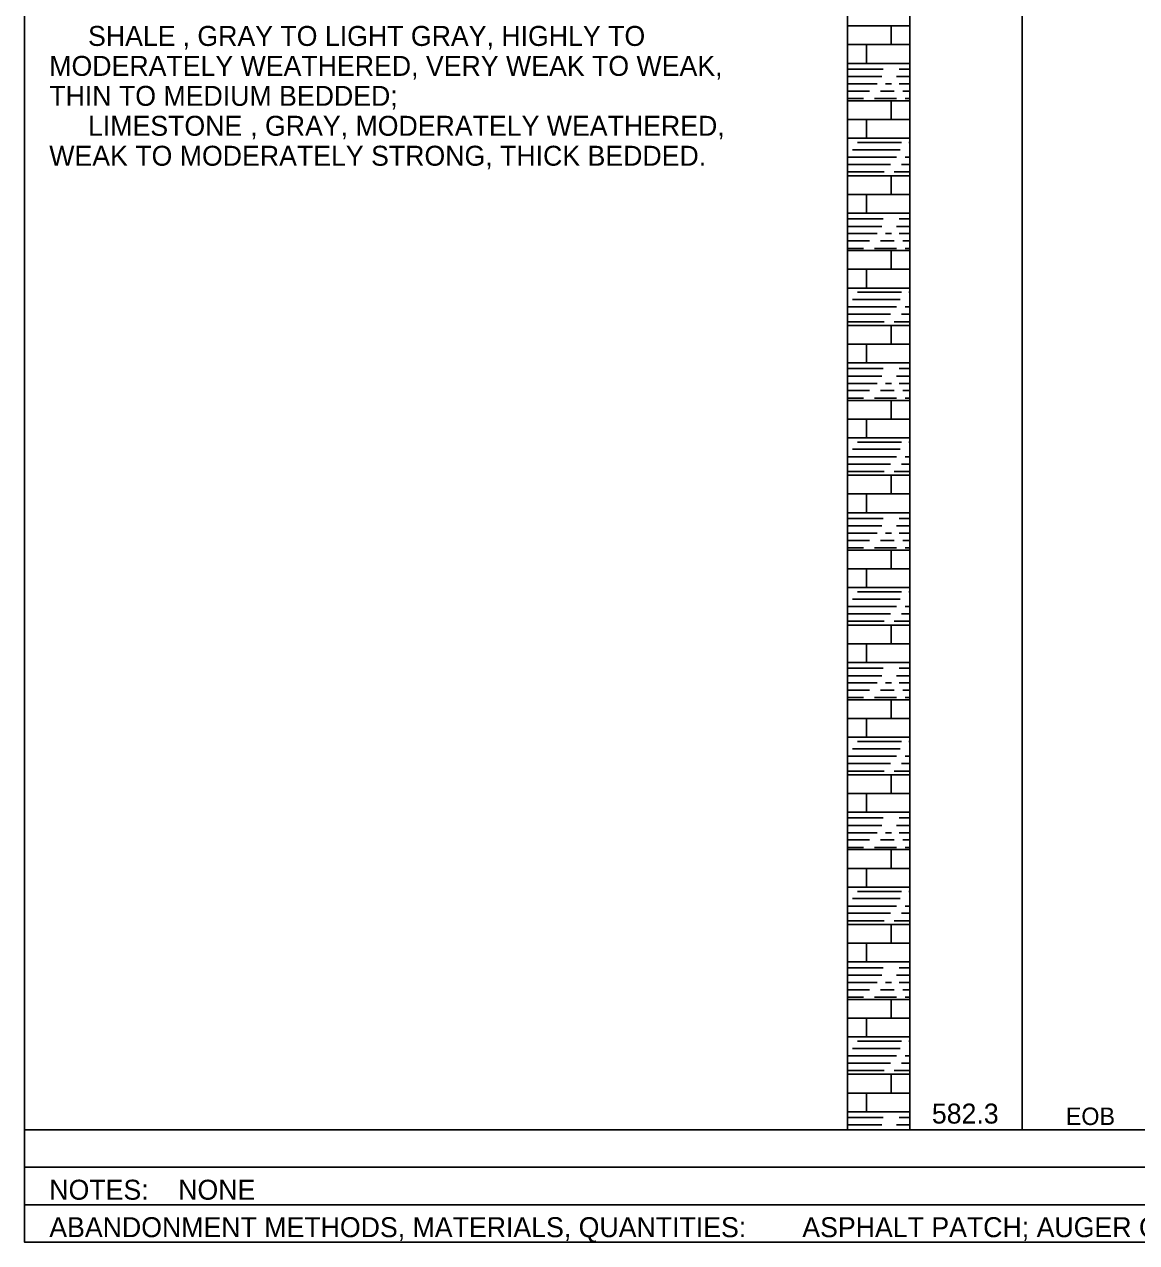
# Model space of a CAD drawing. Extents: x 0 to 0.833, y -0.323 to 0.608.
# Drawn here: x 0 to 0.3715, y -0.3234 to 0.0833 of the extents above; entities that cross this region are included whole.
import ezdxf

# ---------------------------------------------------------------- set-up
doc = ezdxf.new("R2010")
doc.units = 0

msp = doc.modelspace()

# ---------------------------------------------------------------- linework, layer by layer
msp.add_lwpolyline([(0, -0.32328), (0.83333, -0.32328), (0.83333, 0.60833), (0, 0.60833)], close=True)
for points in [[(0.29583, 0.55417), (0.29583, -0.28575)], [(0.29583, 0.55417), (0.29583, -0.28575)], [(0.33333, 0.55417), (0.33333, -0.28575)], [(0.33333, 0.55417), (0.33333, -0.28575)], [(0.275, 0.52917), (0.275, -0.28575)], [(0.275, 0.09525), (0.275, -0.28575)], [(0.275, 0.08275), (0.29583, 0.08275)], [(0.28958, 0.0765), (0.28958, 0.08275)], [(0.275, 0.0765), (0.29583, 0.0765)], [(0.28125, 0.07025), (0.28125, 0.0765)], [(0.275, 0.07025), (0.29583, 0.07025)], [(0.275, 0.06833), (0.28683, 0.06833)], [(0.275, 0.06583), (0.28642, 0.06583)], [(0.29133, 0.06583), (0.29583, 0.06583)], [(0.29217, 0.06833), (0.29583, 0.06833)], [(0.275, 0.06342), (0.28483, 0.06342)], [(0.28767, 0.06342), (0.28967, 0.06342)], [(0.29217, 0.06342), (0.29583, 0.06342)], [(0.275, 0.061), (0.28233, 0.061)], [(0.275, 0.0585), (0.28033, 0.0585)], [(0.275, 0.05775), (0.29583, 0.05775)], [(0.284, 0.0585), (0.29133, 0.0585)], [(0.286, 0.061), (0.2905, 0.061)], [(0.28958, 0.0515), (0.28958, 0.05775)], [(0.29342, 0.061), (0.29583, 0.061)], [(0.29417, 0.0585), (0.29583, 0.0585)], [(0.275, 0.0515), (0.29583, 0.0515)], [(0.28125, 0.04525), (0.28125, 0.0515)], [(0.275, 0.04525), (0.29583, 0.04525)], [(0.27667, 0.04142), (0.29258, 0.04142)], [(0.27825, 0.04383), (0.293, 0.04383)], [(0.29542, 0.04383), (0.29583, 0.04383)], [(0.275, 0.03892), (0.29133, 0.03892)], [(0.29417, 0.03892), (0.29583, 0.03892)], [(0.275, 0.0365), (0.28933, 0.0365)], [(0.275, 0.034), (0.28725, 0.034)], [(0.275, 0.03275), (0.29583, 0.03275)], [(0.28958, 0.0265), (0.28958, 0.03275)], [(0.2905, 0.034), (0.29583, 0.034)], [(0.293, 0.0365), (0.29583, 0.0365)], [(0.275, 0.0265), (0.29583, 0.0265)], [(0.28125, 0.02025), (0.28125, 0.0265)], [(0.275, 0.02025), (0.29583, 0.02025)], [(0.275, 0.01833), (0.28683, 0.01833)], [(0.29217, 0.01833), (0.29583, 0.01833)], [(0.275, 0.01583), (0.28642, 0.01583)], [(0.275, 0.01342), (0.28483, 0.01342)], [(0.28767, 0.01342), (0.28967, 0.01342)], [(0.29133, 0.01583), (0.29583, 0.01583)], [(0.29217, 0.01342), (0.29583, 0.01342)], [(0.275, 0.011), (0.28233, 0.011)], [(0.275, 0.0085), (0.28033, 0.0085)], [(0.284, 0.0085), (0.29133, 0.0085)], [(0.286, 0.011), (0.2905, 0.011)], [(0.29342, 0.011), (0.29583, 0.011)], [(0.29417, 0.0085), (0.29583, 0.0085)], [(0.275, 0.00775), (0.29583, 0.00775)], [(0.28958, 0.0015), (0.28958, 0.00775)], [(0.275, 0.0015), (0.29583, 0.0015)], [(0.28125, -0.00475), (0.28125, 0.0015)], [(0.275, -0.00475), (0.29583, -0.00475)], [(0.27825, -0.00617), (0.293, -0.00617)], [(0.29542, -0.00617), (0.29583, -0.00617)], [(0.275, -0.01108), (0.29133, -0.01108)], [(0.27667, -0.00858), (0.29258, -0.00858)], [(0.29417, -0.01108), (0.29583, -0.01108)], [(0.275, -0.0135), (0.28933, -0.0135)], [(0.275, -0.016), (0.28725, -0.016)], [(0.2905, -0.016), (0.29583, -0.016)], [(0.293, -0.0135), (0.29583, -0.0135)], [(0.275, -0.01725), (0.29583, -0.01725)], [(0.28958, -0.0235), (0.28958, -0.01725)], [(0.275, -0.0235), (0.29583, -0.0235)], [(0.28125, -0.02975), (0.28125, -0.0235)], [(0.275, -0.02975), (0.29583, -0.02975)], [(0.275, -0.03167), (0.28683, -0.03167)], [(0.29217, -0.03167), (0.29583, -0.03167)], [(0.275, -0.03417), (0.28642, -0.03417)], [(0.275, -0.03658), (0.28483, -0.03658)], [(0.28767, -0.03658), (0.28967, -0.03658)], [(0.29133, -0.03417), (0.29583, -0.03417)], [(0.29217, -0.03658), (0.29583, -0.03658)], [(0.275, -0.039), (0.28233, -0.039)], [(0.286, -0.039), (0.2905, -0.039)], [(0.29342, -0.039), (0.29583, -0.039)], [(0.275, -0.0415), (0.28033, -0.0415)], [(0.275, -0.04225), (0.29583, -0.04225)], [(0.284, -0.0415), (0.29133, -0.0415)], [(0.28958, -0.0485), (0.28958, -0.04225)], [(0.29417, -0.0415), (0.29583, -0.0415)], [(0.275, -0.0485), (0.29583, -0.0485)], [(0.28125, -0.05475), (0.28125, -0.0485)], [(0.275, -0.05475), (0.29583, -0.05475)], [(0.27825, -0.05617), (0.293, -0.05617)], [(0.29542, -0.05617), (0.29583, -0.05617)], [(0.27667, -0.05858), (0.29258, -0.05858)], [(0.275, -0.06108), (0.29133, -0.06108)], [(0.275, -0.0635), (0.28933, -0.0635)], [(0.293, -0.0635), (0.29583, -0.0635)], [(0.29417, -0.06108), (0.29583, -0.06108)], [(0.275, -0.066), (0.28725, -0.066)], [(0.275, -0.06725), (0.29583, -0.06725)], [(0.28958, -0.0735), (0.28958, -0.06725)], [(0.2905, -0.066), (0.29583, -0.066)], [(0.275, -0.0735), (0.29583, -0.0735)], [(0.28125, -0.07975), (0.28125, -0.0735)], [(0.275, -0.07975), (0.29583, -0.07975)], [(0.275, -0.08167), (0.28683, -0.08167)], [(0.275, -0.08417), (0.28642, -0.08417)], [(0.29133, -0.08417), (0.29583, -0.08417)], [(0.29217, -0.08167), (0.29583, -0.08167)], [(0.275, -0.08658), (0.28483, -0.08658)], [(0.275, -0.089), (0.28233, -0.089)], [(0.286, -0.089), (0.2905, -0.089)], [(0.28767, -0.08658), (0.28967, -0.08658)], [(0.29217, -0.08658), (0.29583, -0.08658)], [(0.29342, -0.089), (0.29583, -0.089)], [(0.275, -0.0915), (0.28033, -0.0915)], [(0.275, -0.09225), (0.29583, -0.09225)], [(0.284, -0.0915), (0.29133, -0.0915)], [(0.28958, -0.0985), (0.28958, -0.09225)], [(0.29417, -0.0915), (0.29583, -0.0915)], [(0.275, -0.0985), (0.29583, -0.0985)], [(0.28125, -0.10475), (0.28125, -0.0985)], [(0.275, -0.10475), (0.29583, -0.10475)], [(0.27667, -0.10858), (0.29258, -0.10858)], [(0.27825, -0.10617), (0.293, -0.10617)], [(0.29542, -0.10617), (0.29583, -0.10617)], [(0.275, -0.11108), (0.29133, -0.11108)], [(0.275, -0.1135), (0.28933, -0.1135)], [(0.293, -0.1135), (0.29583, -0.1135)], [(0.29417, -0.11108), (0.29583, -0.11108)], [(0.275, -0.116), (0.28725, -0.116)], [(0.275, -0.11725), (0.29583, -0.11725)], [(0.28958, -0.1235), (0.28958, -0.11725)], [(0.2905, -0.116), (0.29583, -0.116)], [(0.275, -0.1235), (0.29583, -0.1235)], [(0.28125, -0.12975), (0.28125, -0.1235)], [(0.275, -0.12975), (0.29583, -0.12975)], [(0.275, -0.13167), (0.28683, -0.13167)], [(0.275, -0.13417), (0.28642, -0.13417)], [(0.29133, -0.13417), (0.29583, -0.13417)], [(0.29217, -0.13167), (0.29583, -0.13167)], [(0.275, -0.13658), (0.28483, -0.13658)], [(0.28767, -0.13658), (0.28967, -0.13658)], [(0.29217, -0.13658), (0.29583, -0.13658)], [(0.275, -0.139), (0.28233, -0.139)], [(0.275, -0.1415), (0.28033, -0.1415)], [(0.275, -0.14225), (0.29583, -0.14225)], [(0.284, -0.1415), (0.29133, -0.1415)], [(0.286, -0.139), (0.2905, -0.139)], [(0.28958, -0.1485), (0.28958, -0.14225)], [(0.29342, -0.139), (0.29583, -0.139)], [(0.29417, -0.1415), (0.29583, -0.1415)], [(0.275, -0.1485), (0.29583, -0.1485)], [(0.28125, -0.15475), (0.28125, -0.1485)], [(0.275, -0.15475), (0.29583, -0.15475)], [(0.27667, -0.15858), (0.29258, -0.15858)], [(0.27825, -0.15617), (0.293, -0.15617)], [(0.29542, -0.15617), (0.29583, -0.15617)], [(0.275, -0.16108), (0.29133, -0.16108)], [(0.29417, -0.16108), (0.29583, -0.16108)], [(0.275, -0.1635), (0.28933, -0.1635)], [(0.275, -0.166), (0.28725, -0.166)], [(0.2905, -0.166), (0.29583, -0.166)], [(0.293, -0.1635), (0.29583, -0.1635)], [(0.275, -0.16725), (0.29583, -0.16725)], [(0.28958, -0.1735), (0.28958, -0.16725)], [(0.275, -0.1735), (0.29583, -0.1735)], [(0.28125, -0.17975), (0.28125, -0.1735)], [(0.275, -0.17975), (0.29583, -0.17975)], [(0.275, -0.18167), (0.28683, -0.18167)], [(0.29217, -0.18167), (0.29583, -0.18167)], [(0.275, -0.18417), (0.28642, -0.18417)], [(0.275, -0.18658), (0.28483, -0.18658)], [(0.28767, -0.18658), (0.28967, -0.18658)], [(0.29133, -0.18417), (0.29583, -0.18417)], [(0.29217, -0.18658), (0.29583, -0.18658)], [(0.275, -0.189), (0.28233, -0.189)], [(0.286, -0.189), (0.2905, -0.189)], [(0.29342, -0.189), (0.29583, -0.189)], [(0.275, -0.1915), (0.28033, -0.1915)], [(0.275, -0.19225), (0.29583, -0.19225)], [(0.284, -0.1915), (0.29133, -0.1915)], [(0.28958, -0.1985), (0.28958, -0.19225)], [(0.29417, -0.1915), (0.29583, -0.1915)], [(0.275, -0.1985), (0.29583, -0.1985)], [(0.28125, -0.20475), (0.28125, -0.1985)], [(0.275, -0.20475), (0.29583, -0.20475)], [(0.27825, -0.20617), (0.293, -0.20617)], [(0.29542, -0.20617), (0.29583, -0.20617)], [(0, -0.21078), (0, -0.32328), (0.83333, -0.32328), (0.83333, -0.21078)], [(0.275, -0.21108), (0.29133, -0.21108)], [(0.27667, -0.20858), (0.29258, -0.20858)], [(0.29417, -0.21108), (0.29583, -0.21108)], [(0.275, -0.2135), (0.28933, -0.2135)], [(0.293, -0.2135), (0.29583, -0.2135)], [(0.275, -0.216), (0.28725, -0.216)], [(0.275, -0.21725), (0.29583, -0.21725)], [(0.28958, -0.2235), (0.28958, -0.21725)], [(0.2905, -0.216), (0.29583, -0.216)], [(0.275, -0.2235), (0.29583, -0.2235)], [(0.28125, -0.22975), (0.28125, -0.2235)], [(0.275, -0.22975), (0.29583, -0.22975)], [(0.275, -0.23167), (0.28683, -0.23167)], [(0.29217, -0.23167), (0.29583, -0.23167)], [(0.275, -0.23417), (0.28642, -0.23417)], [(0.29133, -0.23417), (0.29583, -0.23417)], [(0.275, -0.23658), (0.28483, -0.23658)], [(0.275, -0.239), (0.28233, -0.239)], [(0.286, -0.239), (0.2905, -0.239)], [(0.28767, -0.23658), (0.28967, -0.23658)], [(0.29217, -0.23658), (0.29583, -0.23658)], [(0.29342, -0.239), (0.29583, -0.239)], [(0.275, -0.2415), (0.28033, -0.2415)], [(0.275, -0.24225), (0.29583, -0.24225)], [(0.284, -0.2415), (0.29133, -0.2415)], [(0.28958, -0.2485), (0.28958, -0.24225)], [(0.29417, -0.2415), (0.29583, -0.2415)], [(0.275, -0.2485), (0.29583, -0.2485)], [(0.28125, -0.25475), (0.28125, -0.2485)], [(0.275, -0.25475), (0.29583, -0.25475)], [(0.27825, -0.25617), (0.293, -0.25617)], [(0.29542, -0.25617), (0.29583, -0.25617)], [(0.27667, -0.25858), (0.29258, -0.25858)], [(0.275, -0.26108), (0.29133, -0.26108)], [(0.275, -0.2635), (0.28933, -0.2635)], [(0.293, -0.2635), (0.29583, -0.2635)], [(0.29417, -0.26108), (0.29583, -0.26108)], [(0.275, -0.266), (0.28725, -0.266)], [(0.275, -0.26725), (0.29583, -0.26725)], [(0.28958, -0.2735), (0.28958, -0.26725)], [(0.2905, -0.266), (0.29583, -0.266)], [(0.275, -0.2735), (0.29583, -0.2735)], [(0.28125, -0.27975), (0.28125, -0.2735)], [(0.275, -0.27975), (0.29583, -0.27975)], [(0.275, -0.28167), (0.28683, -0.28167)], [(0.275, -0.28417), (0.28642, -0.28417)], [(0.29133, -0.28417), (0.29583, -0.28417)], [(0.29217, -0.28167), (0.29583, -0.28167)], [(0, -0.28575), (0.275, -0.28575)], [(0.275, -0.28575), (0.29583, -0.28575)], [(0.275, -0.28575), (0.29583, -0.28575)], [(0.29583, -0.28575), (0.33333, -0.28575)], [(0.33333, -0.28575), (0.37917, -0.28575)], [(0, -0.29828), (0.83333, -0.29828)], [(0, -0.31078), (0.83333, -0.31078)]]:
    msp.add_lwpolyline(points)

# ---------------------------------------------------------------- texts
for s, height, p in [('SHALE', 0.006667, (0.02127, 0.07608)), (', GRAY TO LIGHT GRAY, HIGHLY TO', 0.0066667, (0.05284, 0.07608)), ('MODERATELY WEATHERED, VERY WEAK TO WEAK,', 0.0066667, (0.00833, 0.06608)), ('THIN TO MEDIUM BEDDED;', 0.0066667, (0.00833, 0.05608)), ('LIMESTONE', 0.006667, (0.02127, 0.04608)), (', GRAY, MODERATELY WEATHERED,', 0.0066667, (0.07544, 0.04608)), ('WEAK TO MODERATELY STRONG, THICK BEDDED.', 0.0066667, (0.00833, 0.03608)), ('582.3', 0.006667, (0.30314, -0.2837)), ('EOB', 0.005833, (0.34786, -0.28418)), ('NOTES:', 0.006667, (0.00833, -0.30912)), ('NONE', 0.006667, (0.05139, -0.30912)), ('ABANDONMENT METHODS, MATERIALS, QUANTITIES:', 0.0066667, (0.00833, -0.32162)), ('ASPHALT PATCH; AUGER CUTTINGS MIXED WITH   BENTONITE CHIPS', 0.0066667, (0.25986, -0.32162))]:
    msp.add_text(s, height=height).set_placement(p)

doc.saveas('drawing.dxf')
